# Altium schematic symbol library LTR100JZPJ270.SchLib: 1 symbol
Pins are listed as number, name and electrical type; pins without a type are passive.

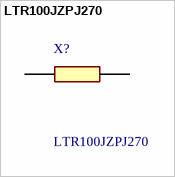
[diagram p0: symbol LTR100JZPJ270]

## LTR100JZPJ270
designator X?
27 Ohms +/-5% 3W Chip Resistor Wide 2512 (6432 Metric), 1225 Automotive AEC-Q200, Pulse Withstanding Thick Film; Manufacturer_Name: ROHM Semiconductor; Geometry.Height: 0.7mm
footprint RESC3264X70N
pins: 1, 2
